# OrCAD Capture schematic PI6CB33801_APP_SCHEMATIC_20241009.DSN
size B; title: PI6CB33801/2 Application schematic; rev: 1.0; note: Diodes Inc. Clock IC Application Engineering
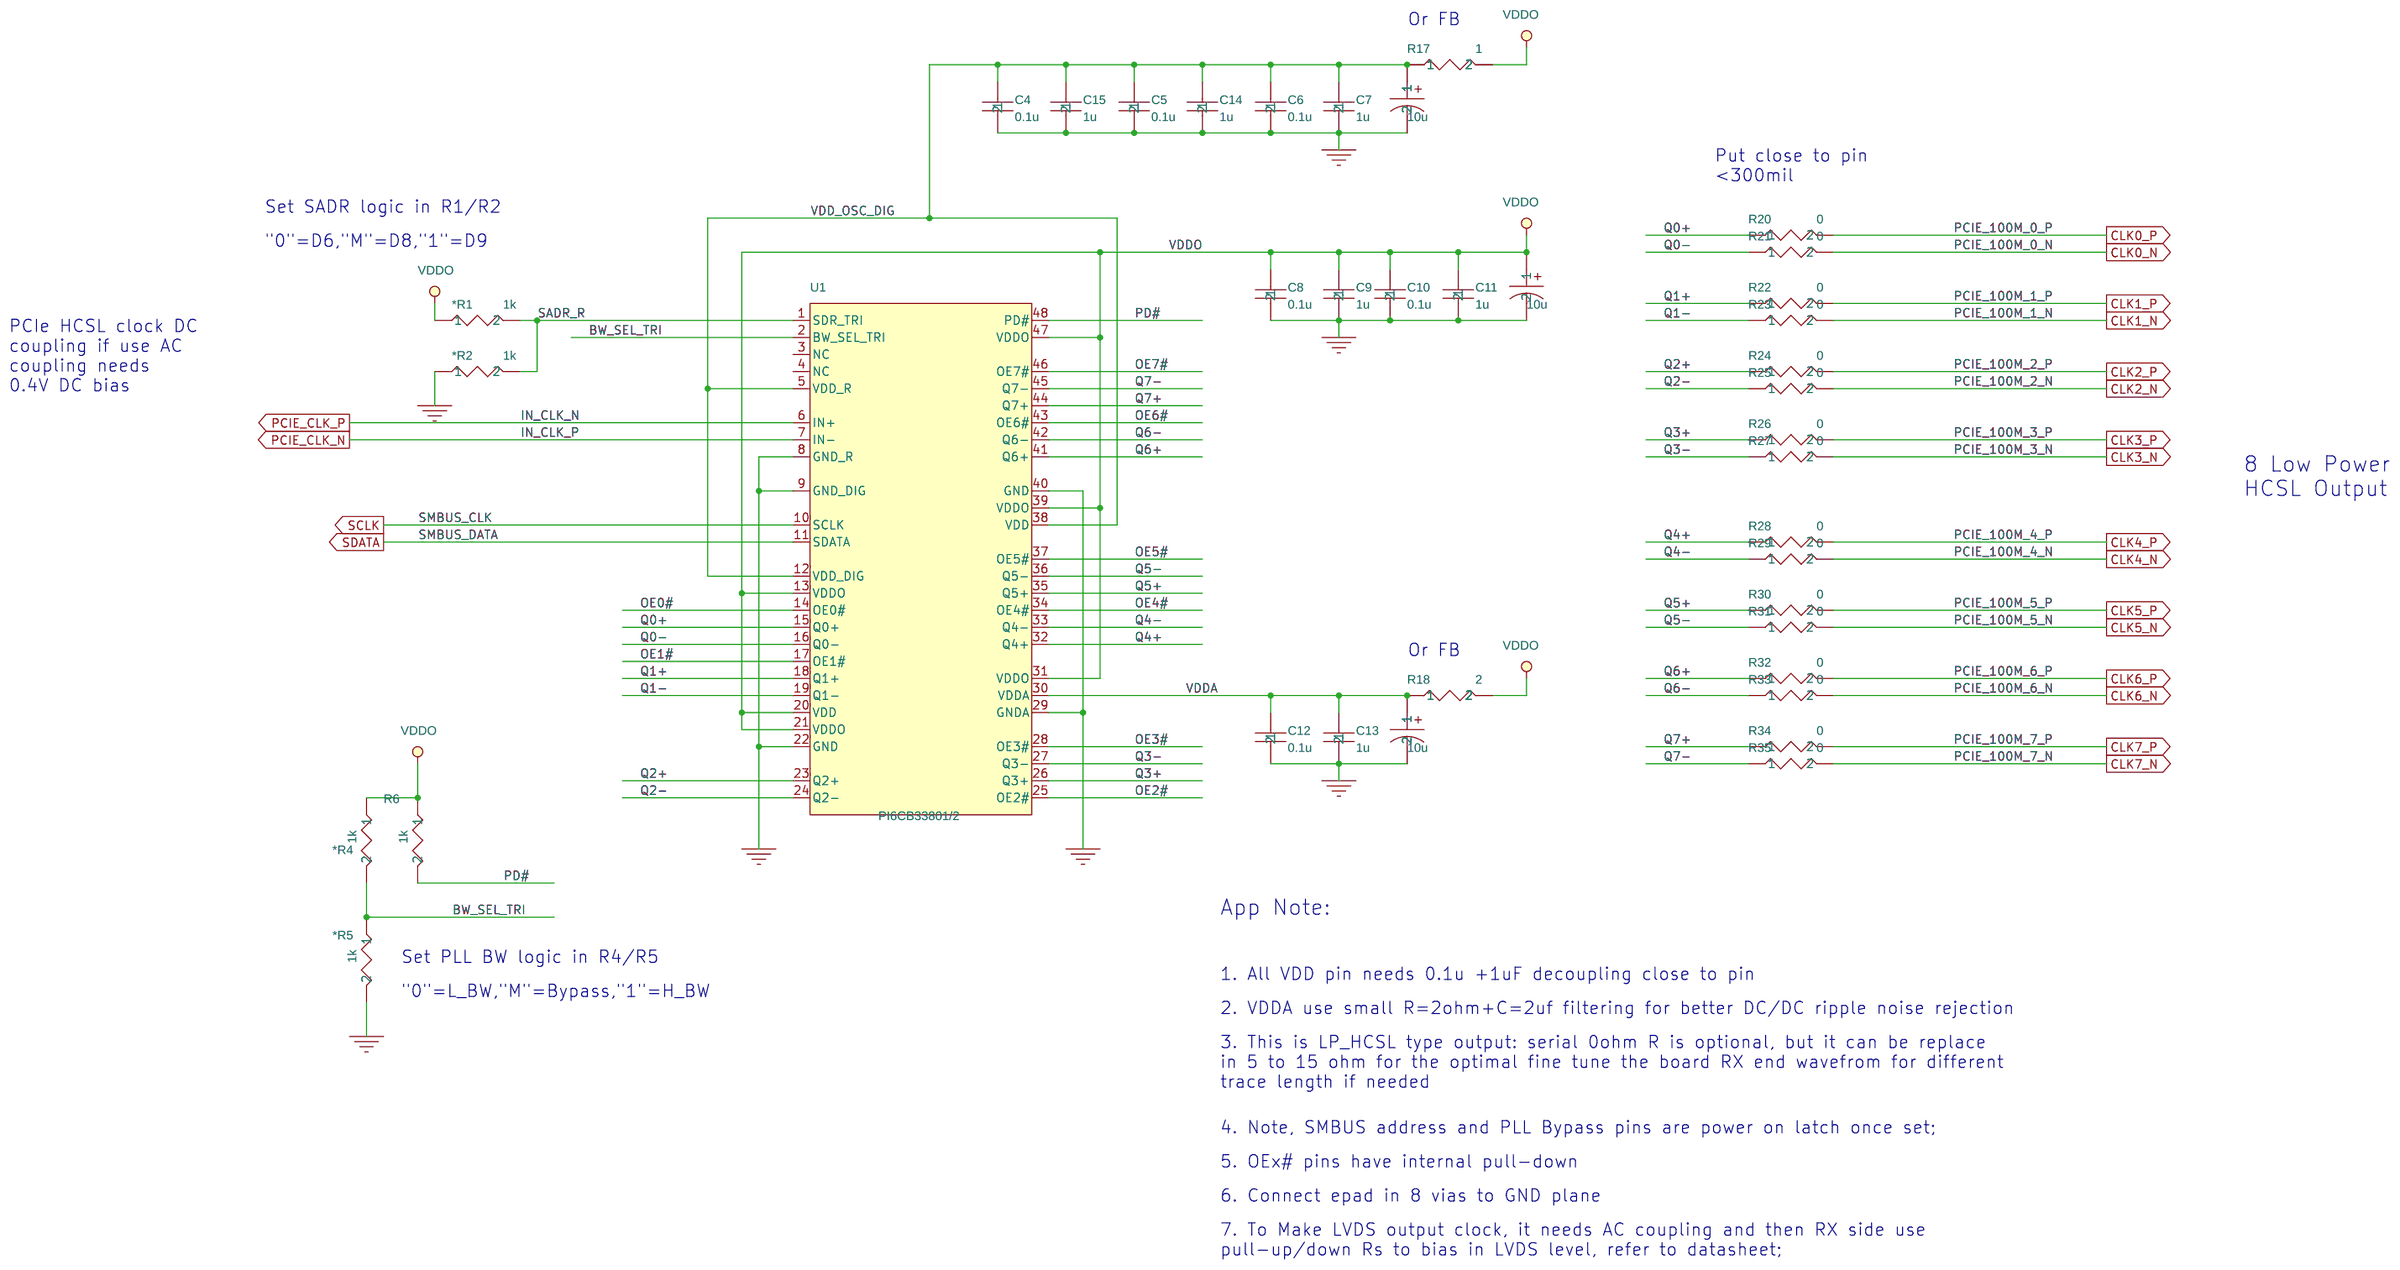
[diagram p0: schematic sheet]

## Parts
*R1  1k  [R_0402]
*R2  1k  [R_0402]
*R4  1k  [R_0402]
*R5  1k  [R_0402]
C4  0.1u  [CC_0402]
C5  0.1u  [CC_0402]
C6  0.1u  [CC_0402]
C7  1u  [CC_0402]
C8  0.1u  [CC_0402]
C9  1u  [CC_0402]
C10  0.1u  [CC_0402]
C11  1u  [CC_0402]
C12  0.1u  [CC_0402]
C13  1u  [CC_0402]
C14  1u  [CC_0402]
C15  1u  [CC_0402]
EC1  10u  [CAP1000UF]
EC1#2  10u  [CAP1000UF]
EC1#3  10u  [CAP1000UF]
R6  1k  [R_0402]
R17  1  [R_0402]
R18  2  [R_0402]
R20  0  [R_0402]
R21  0  [R_0402]
R22  0  [R_0402]
R23  0  [R_0402]
R24  0  [R_0402]
R25  0  [R_0402]
R26  0  [R_0402]
R27  0  [R_0402]
R28  0  [R_0402]
R29  0  [R_0402]
R30  0  [R_0402]
R31  0  [R_0402]
R32  0  [R_0402]
R33  0  [R_0402]
R34  0  [R_0402]
R35  0  [R_0402]
U1  PI6CB33801/2  [TSSOP20]

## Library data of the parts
*R1 = R_0402_4
*R2 = R_0402_3
*R4 = R_0402_14
*R5 = R_0402_10
C4 = C_0.1u_0402_4
C5 = C_0.1u_0402_5
C6 = C_0.1u_0402_1
C7 = C_0.1u_0402_10
C8 = C_0.1u_0402_2
C9 = C_0.1u_0402_8
C10 = C_0.1u_0402_3
C11 = C_0.1u_0402
C12 = C_0.1u_0402_6
C13 = C_0.1u_0402_11
C14 = C_0.1u_0402_9
C15 = C_0.1u_0402_7
EC1 = C_alum_1000u_2
EC1#2 EC1#3 = C_alum_1000u
R6 = R_0402_9
R17 = R_0402_2
R18 = R_0402_13
R20 = R_0402_7
R21 = R_0402_1
R22 = R_0402_20
R23 = R_0402_12
R24 = R_0402_21
R25 = R_0402_18
R26 = R_0402_15
R27 = R_0402_17
R28 = R_0402_16
R29 = R_0402
R30 = R_0402_8
R31 = R_0402_6
R32 = R_0402_22
R33 = R_0402_19
R34 = R_0402_5
R35 = R_0402_11
U1 = PI6CFGL402BLIE_20

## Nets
3.3V: *R1.1 *R4.1 C8.1 C9.1 C10.1 C11.1 EC1#2.1 R6.1 R17.2 R18.2 U1.13(VDDO) U1.20(VDD) U1.21(VDDO) U1.31(VDDO) U1.39(VDDO) U1.47(VDDO)
GND: *R2.1 *R5.2 C4.2 C5.2 C6.2 C7.2 C8.2 C9.2 C10.2 C11.2 C12.2 C13.2 C14.2 C15.2 EC1.2 EC1#2.2 EC1#3.2 U1.8(GND_R) U1.9(GND_DIG) U1.22(GND) U1.29(GNDA) U1.40(GND)
VDD_OSC_DIG: C4.1 C5.1 C6.1 C7.1 C14.1 C15.1 EC1#3.1 R17.1 U1.5(VDD_R) U1.12(VDD_DIG) U1.38(VDD)
VDDA: C12.1 C13.1 EC1.1 R18.1 U1.30(VDDA)
BW_SEL_TRI: *R4.2 *R5.1 U1.2(BW_SEL_TRI)
CLK0_N: R21.2
CLK0_P: R20.2
CLK1_N: R23.2
CLK1_P: R22.2
CLK2_N: R25.2
CLK2_P: R24.2
CLK3_N: R27.2
CLK3_P: R26.2
CLK4_N: R29.2
CLK4_P: R28.2
CLK5_N: R31.2
CLK5_P: R30.2
CLK6_N: R33.2
CLK6_P: R32.2
CLK7_N: R35.2
CLK7_P: R34.2
OE0#: U1.14(OE0#)
OE1#: U1.17(OE1#)
OE2#: U1.25(OE2#)
OE3#: U1.28(OE3#)
OE4#: U1.34(OE4#)
OE5#: U1.37(OE5#)
OE6#: U1.43(OE6#)
OE7#: U1.46(OE7#)
PCIE_CLK_N: U1.7(IN-)
PCIE_CLK_P: U1.6(IN+)
PD#: R6.2 U1.48(PD#)
Q0+: R20.1 U1.15(Q0+)
Q0-: R21.1 U1.16(Q0-)
Q1+: R22.1 U1.18(Q1+)
Q1-: R23.1 U1.19(Q1-)
Q2+: R24.1 U1.23(Q2+)
Q2-: R25.1 U1.24(Q2-)
Q3+: R26.1 U1.26(Q3+)
Q3-: R27.1 U1.27(Q3-)
Q4+: R28.1 U1.32(Q4+)
Q4-: R29.1 U1.33(Q4-)
Q5+: R30.1 U1.35(Q5+)
Q5-: R31.1 U1.36(Q5-)
Q6+: R32.1 U1.41(Q6+)
Q6-: R33.1 U1.42(Q6-)
Q7+: R34.1 U1.44(Q7+)
Q7-: R35.1 U1.45(Q7-)
SADR_R: *R1.2 *R2.2 U1.1(SDR_TRI)
SCLK: U1.10(SCLK)
SDATA: U1.11(SDATA)

Not connected (* = marked no-connect by the designer): U1 3(NC) 4(NC)

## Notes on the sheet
- Or FB
- Put close to pin
  <300mil
- Set SADR logic in R1/R2
- "0"=D6,"M"=D8,"1"=D9
- PCIe HCSL clock DC
  coupling if use AC
  coupling needs
  0.4V DC bias
- 8 Low Power
  HCSL Output
- Or FB
- App Note:
- Set PLL BW logic in R4/R5
- 1. All VDD pin needs 0.1u +1uF decoupling close to pin
- "0"=L_BW,"M"=Bypass,"1"=H_BW
- 2. VDDA use small R=2ohm+C=2uf filtering for better DC/DC ripple noise rejection
- 3. This is LP_HCSL type output: serial 0ohm R is optional, but it can be replace
  in 5 to 15 ohm for the optimal fine tune the board RX end wavefrom for different
  trace length if needed
- 4. Note, SMBUS address and PLL Bypass pins are power on latch once set;
- 5. OEx# pins have internal pull-down
- 6. Connect epad in 8 vias to GND plane
- 7. To Make LVDS output clock, it needs AC coupling and then RX side use
  pull-up/down Rs to bias in LVDS level, refer to datasheet;
